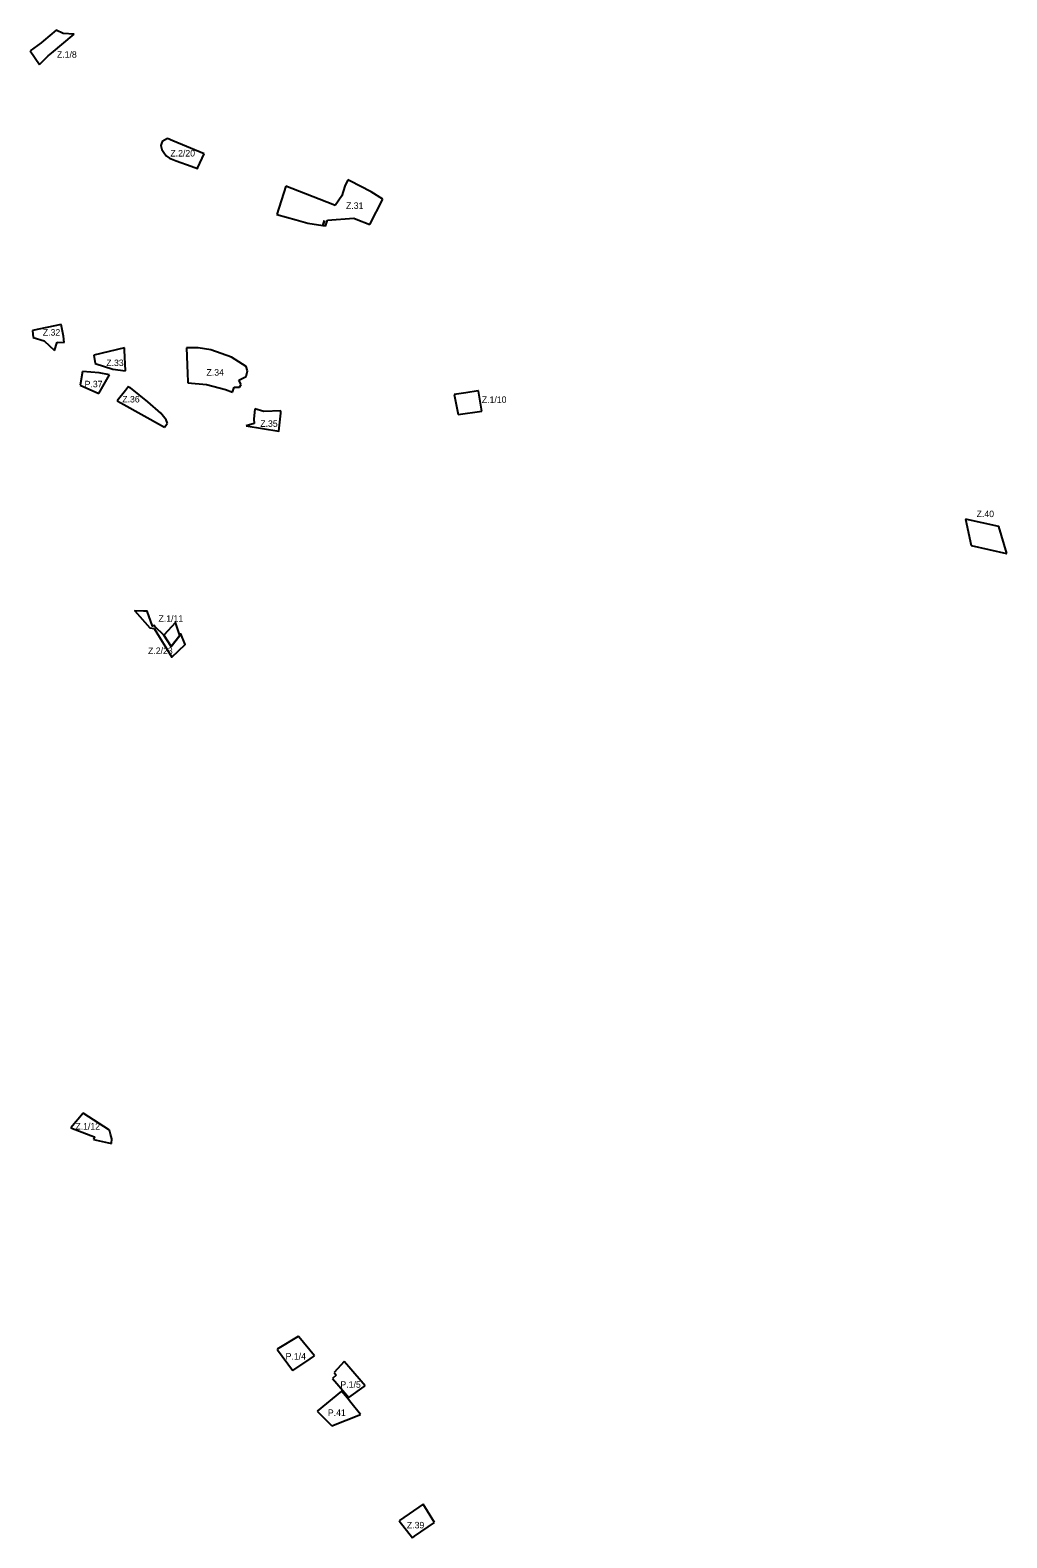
# Model space of a CAD drawing. Extents: x -438701 to -435614, y -1126017 to -1121766.
# Drawn here: x -437116 to -435614, y -1126017 to -1123697 of the extents above; entities that cross this region are included whole.
import ezdxf

# ---------------------------------------------------------------- set-up
doc = ezdxf.new("R2010")
doc.units = 0
for name, color, linetype in [('NAVRH', 7, 'Continuous'), ('STAV', 7, 'Continuous'), ('Vrstva 3', 7, 'Continuous'), ('Vrstva 6', 7, 'Continuous'), ('Vrstva 7', 7, 'Continuous'), ('Vrstva 9', 7, 'Continuous')]:
    doc.layers.add(name, color=color, linetype=linetype)

msp = doc.modelspace()

# ---------------------------------------------------------------- linework, layer by layer
at = {"layer": 'NAVRH'}
for p, q in [((-437083.4, -1123732.5), (-437048.4, -1123703.3)), ((-437048.4, -1123703.3), (-437065.4, -1123702.4)), ((-437099.4, -1123716.9), (-437116.3, -1123729)), ((-437116.3, -1123729), (-437101.9, -1123750.4)), ((-437095.9, -1123713.9), (-437099.4, -1123716.9)), ((-437101.9, -1123750.4), (-437088.6, -1123737)), ((-437088.6, -1123737), (-437083.4, -1123732.5)), ((-436905.2, -1123864.2), (-436913, -1123868.5)), ((-436896.8, -1123867.7), (-436905.2, -1123864.2)), ((-436848.6, -1123887.5), (-436896.8, -1123867.7)), ((-436858.2, -1123908.4), (-436848.6, -1123887.5)), ((-436902.2, -1123894.4), (-436891.8, -1123898.2)), ((-436891.8, -1123898.2), (-436868.4, -1123906.8)), ((-436722.9, -1123937.2), (-436736.8, -1123981)), ((-436650.9, -1123965.6), (-436722.9, -1123937.2)), ((-436632.1, -1123937.3), (-436636.8, -1123952)), ((-436627.7, -1123927.6), (-436632.1, -1123937.3)), ((-436624.3, -1123929.2), (-436627.7, -1123927.6)), ((-436591.6, -1123946.3), (-436624.3, -1123929.2)), ((-436636.8, -1123952), (-436647.2, -1123967)), ((-436593.6, -1123996.5), (-436574, -1123957.5)), ((-436574, -1123957.5), (-436591.6, -1123946.3)), ((-436736.8, -1123981), (-436707, -1123989.2)), ((-436647.2, -1123967), (-436650.9, -1123965.6)), ((-436707, -1123989.2), (-436689.2, -1123994.1)), ((-436689.2, -1123994.1), (-436666.1, -1123998)), ((-436666.1, -1123998), (-436663.7, -1123989.9)), ((-436663.7, -1123989.9), (-436666.1, -1123998)), ((-436666.1, -1123998), (-436662.4, -1123998.6)), ((-436662.4, -1123998.6), (-436661.9, -1123998.7)), ((-436661.9, -1123998.7), (-436659.1, -1123989.5)), ((-436659.1, -1123989.5), (-436618.6, -1123986.4)), ((-436618.6, -1123986.4), (-436614.7, -1123988.1)), ((-436614.7, -1123988.1), (-436593.6, -1123996.5)), ((-437068.7, -1124150.4), (-437112.6, -1124159.2)), ((-437112.6, -1124159.2), (-437111.6, -1124170.1)), ((-437065, -1124168.2), (-437068.7, -1124150.4)), ((-437064, -1124177.9), (-437065, -1124168.2)), ((-437111.6, -1124170.1), (-437094.7, -1124175.4)), ((-437094.7, -1124175.4), (-437079.1, -1124190.4)), ((-437079.1, -1124190.4), (-437074.6, -1124177.5)), ((-437074.6, -1124177.5), (-437064, -1124177.9)), ((-436971.4, -1124186), (-437018.1, -1124197.5)), ((-436858.1, -1124186.2), (-436875.8, -1124186.2)), ((-436875.8, -1124186.2), (-436874.4, -1124225.7)), ((-436838.3, -1124189.2), (-436858.1, -1124186.2)), ((-436806.4, -1124200.6), (-436838.3, -1124189.2)), ((-437018.1, -1124197.5), (-437016.3, -1124210.4)), ((-437016.3, -1124210.4), (-436989, -1124218.8)), ((-436989, -1124218.8), (-436969.5, -1124221.3)), ((-436795.2, -1124235.9), (-436783.9, -1124229.9)), ((-436791.6, -1124242.4), (-436795.2, -1124235.9)), ((-436783.9, -1124229.9), (-436782.2, -1124221.6)), ((-436969.8, -1124251.8), (-436982.2, -1124267.5)), ((-436964.8, -1124245.5), (-436969.8, -1124251.8)), ((-436962.5, -1124247.4), (-436964.8, -1124245.5)), ((-436962, -1124247.8), (-436962.5, -1124247.4)), ((-436935.2, -1124269.2), (-436962, -1124247.8)), ((-436873.8, -1124240.1), (-436844.8, -1124242.4)), ((-436844.8, -1124242.4), (-436815.8, -1124250.1)), ((-436815.8, -1124250.1), (-436805.2, -1124254.3)), ((-436805.2, -1124254.3), (-436802.4, -1124246.6)), ((-436802.4, -1124246.6), (-436794.2, -1124246.6)), ((-436794.2, -1124246.6), (-436791.6, -1124242.4)), ((-436445.9, -1124255.1), (-436463.9, -1124257.7)), ((-436463.9, -1124257.7), (-436457.8, -1124288.6)), ((-436426.4, -1124252.6), (-436426.4, -1124252.3)), ((-436982.2, -1124267.5), (-436976.9, -1124270.5)), ((-436976.9, -1124270.5), (-436909.8, -1124308.1)), ((-436915.3, -1124286.8), (-436935.2, -1124269.2)), ((-436770.6, -1124280.1), (-436772.2, -1124295.9)), ((-436756.9, -1124283.9), (-436770.6, -1124280.1)), ((-436730.6, -1124283), (-436756.9, -1124283.9)), ((-436730.9, -1124286.5), (-436730.6, -1124283)), ((-436457.8, -1124288.6), (-436421.7, -1124283.6)), ((-436907.2, -1124296.7), (-436915.3, -1124286.8)), ((-436909.8, -1124308.1), (-436905.9, -1124303.6)), ((-436904.9, -1124302.6), (-436907.2, -1124296.7)), ((-436905.9, -1124303.6), (-436904.9, -1124302.6)), ((-436771.6, -1124302.6), (-436784.1, -1124306.3)), ((-436772.2, -1124295.9), (-436771.6, -1124302.6)), ((-436733.1, -1124309.7), (-436730.9, -1124286.5)), ((-435677.7, -1124449.5), (-435668.6, -1124490.1)), ((-437034.5, -1125363.7), (-437053.9, -1125386)), ((-436994.4, -1125389.4), (-437034.5, -1125363.7)), ((-437053.9, -1125386), (-437022.8, -1125397.9)), ((-436992.8, -1125395.8), (-436994.4, -1125389.4)), ((-436990.8, -1125403), (-436992.8, -1125395.8)), ((-437018.9, -1125404), (-436991.1, -1125410.3)), ((-436991.1, -1125410.3), (-436990.8, -1125403)), ((-436511.7, -1125965.3), (-436547.9, -1125990.4)), ((-436494.2, -1125993.2), (-436511.7, -1125965.3)), ((-436547.9, -1125990.4), (-436548.7, -1125990.9)), ((-436548.7, -1125990.9), (-436528.2, -1126016.9)), ((-436524.9, -1126014.5), (-436494.2, -1125993.2)), ((-436528.2, -1126016.9), (-436524.9, -1126014.5))]:
    msp.add_line(p, q, dxfattribs=at)
for points in [[(-437065.4, -1123702.4), (-437076.5, -1123697.3), (-437095.9, -1123713.9)], [(-436913, -1123868.5), (-436915.2, -1123874.8), (-436913.5, -1123880.9), (-436910.9, -1123885.7), (-436907.2, -1123890.6), (-436902.2, -1123894.4)], [(-436868.4, -1123906.8), (-436859, -1123910.2), (-436858.2, -1123908.4)], [(-436969.5, -1124221.3), (-436971.2, -1124189.7), (-436971.4, -1124186)], [(-436782.2, -1124221.6), (-436783.8, -1124214.7), (-436806.4, -1124200.6)], [(-436874.4, -1124225.7), (-436873.9, -1124237.6), (-436873.8, -1124240.1)], [(-436426.4, -1124252.3), (-436427, -1124252.4), (-436445.9, -1124255.1)], [(-436421.7, -1124283.6), (-436421.7, -1124283.4), (-436426.4, -1124252.6)], [(-436784.1, -1124306.3), (-436733.8, -1124314.3), (-436733.1, -1124309.7)], [(-435613.9, -1124502.6), (-435626, -1124460.9), (-435677.7, -1124449.5)], [(-435668.6, -1124490.1), (-435614.2, -1124502.5), (-435613.9, -1124502.6)], [(-436910.8, -1124628.3), (-436924.2, -1124615.3), (-436925.2, -1124613), (-436928.1, -1124614.1), (-436936.3, -1124591.2), (-436941.8, -1124591.2), (-436955.5, -1124590.9), (-436932.2, -1124617), (-436925.5, -1124618), (-436898.2, -1124662.2), (-436877.8, -1124642.5), (-436884.3, -1124626.3), (-436886.2, -1124628.7)], [(-436886.2, -1124628.7), (-436892.8, -1124608.8), (-436910.8, -1124628.3)], [(-436886.2, -1124628.7), (-436899.3, -1124645.8), (-436910.8, -1124628.3)], [(-436910.8, -1124628.3), (-436899.3, -1124645.8), (-436886.2, -1124628.7)], [(-437022.8, -1125397.9), (-437017.4, -1125400), (-437018.9, -1125404)]]:
    msp.add_lwpolyline(points, dxfattribs=at)
at = {"layer": 'Vrstva 3'}
for p, q in [((-437036, -1124222.5), (-437039.4, -1124243.7)), ((-437010.4, -1124256.5), (-436994, -1124227.8)), ((-437039.4, -1124243.7), (-437010.4, -1124256.5)), ((-436703.8, -1125707.2), (-436736.4, -1125726.8)), ((-436736.4, -1125726.8), (-436735.8, -1125727.8)), ((-436633.2, -1125745.4), (-436648.8, -1125762.5)), ((-436626.2, -1125753.6), (-436633.2, -1125745.4)), ((-436645.4, -1125766.4), (-436651.2, -1125771.9)), ((-436648.8, -1125762.5), (-436645.4, -1125766.4)), ((-436601.2, -1125782.8), (-436626.2, -1125753.6)), ((-436637.5, -1125791.1), (-436674.7, -1125822.2)), ((-436651.2, -1125771.9), (-436644.8, -1125779.3)), ((-436644.8, -1125779.3), (-436626.2, -1125800.9)), ((-436628.1, -1125802.2), (-436637.5, -1125791.1)), ((-436626.2, -1125800.9), (-436602.6, -1125783.9)), ((-436602.6, -1125783.9), (-436601.2, -1125782.8)), ((-436623.1, -1125808.4), (-436628.1, -1125802.2)), ((-436608.1, -1125827.2), (-436623.1, -1125808.4)), ((-436674.7, -1125822.2), (-436663.5, -1125833.4)), ((-436663.5, -1125833.4), (-436652.4, -1125844.6)), ((-436652.4, -1125844.6), (-436608.1, -1125827.2))]:
    msp.add_line(p, q, dxfattribs=at)
for points in [[(-436994, -1124227.8), (-437009.9, -1124224.6), (-437036, -1124222.5)], [(-436679, -1125736.7), (-436702.8, -1125707.8), (-436703.8, -1125707.2)], [(-436735.8, -1125727.8), (-436712.6, -1125759.1), (-436712.4, -1125759.4)], [(-436712.4, -1125759.4), (-436685.7, -1125741.2), (-436679, -1125736.7)]]:
    msp.add_lwpolyline(points, dxfattribs=at)
at = {"layer": 'Vrstva 6'}
for p, q in [((-437083.4, -1123732.5), (-437048.4, -1123703.3)), ((-437048.4, -1123703.3), (-437065.4, -1123702.4)), ((-437099.4, -1123716.9), (-437116.3, -1123729)), ((-437116.3, -1123729), (-437101.9, -1123750.4)), ((-437095.9, -1123713.9), (-437099.4, -1123716.9)), ((-437101.9, -1123750.4), (-437088.6, -1123737)), ((-437088.6, -1123737), (-437083.4, -1123732.5)), ((-436905.2, -1123864.2), (-436913, -1123868.5)), ((-436896.8, -1123867.7), (-436905.2, -1123864.2)), ((-436848.6, -1123887.5), (-436896.8, -1123867.7)), ((-436858.2, -1123908.4), (-436848.6, -1123887.5)), ((-436902.2, -1123894.4), (-436891.8, -1123898.2)), ((-436891.8, -1123898.2), (-436868.4, -1123906.8)), ((-436722.9, -1123937.2), (-436736.8, -1123981)), ((-436650.9, -1123965.6), (-436722.9, -1123937.2)), ((-436632.1, -1123937.3), (-436636.8, -1123952)), ((-436627.7, -1123927.6), (-436632.1, -1123937.3)), ((-436624.3, -1123929.2), (-436627.7, -1123927.6)), ((-436591.6, -1123946.3), (-436624.3, -1123929.2)), ((-436636.8, -1123952), (-436647.2, -1123967)), ((-436593.6, -1123996.5), (-436574, -1123957.5)), ((-436574, -1123957.5), (-436591.6, -1123946.3)), ((-436736.8, -1123981), (-436707, -1123989.2)), ((-436647.2, -1123967), (-436650.9, -1123965.6)), ((-436707, -1123989.2), (-436689.2, -1123994.1)), ((-436689.2, -1123994.1), (-436666.1, -1123998)), ((-436666.1, -1123998), (-436663.7, -1123989.9)), ((-436663.7, -1123989.9), (-436666.1, -1123998)), ((-436666.1, -1123998), (-436662.4, -1123998.6)), ((-436662.4, -1123998.6), (-436661.9, -1123998.7)), ((-436661.9, -1123998.7), (-436659.1, -1123989.5)), ((-436659.1, -1123989.5), (-436618.6, -1123986.4)), ((-436618.6, -1123986.4), (-436614.7, -1123988.1)), ((-436614.7, -1123988.1), (-436593.6, -1123996.5)), ((-437068.7, -1124150.4), (-437112.6, -1124159.2)), ((-437112.6, -1124159.2), (-437111.6, -1124170.1)), ((-437065, -1124168.2), (-437068.7, -1124150.4)), ((-437064, -1124177.9), (-437065, -1124168.2)), ((-437111.6, -1124170.1), (-437094.7, -1124175.4)), ((-437094.7, -1124175.4), (-437079.1, -1124190.4)), ((-437079.1, -1124190.4), (-437074.6, -1124177.5)), ((-437074.6, -1124177.5), (-437064, -1124177.9)), ((-436971.4, -1124186), (-437018.1, -1124197.5)), ((-436858.1, -1124186.2), (-436875.8, -1124186.2)), ((-436875.8, -1124186.2), (-436874.4, -1124225.7)), ((-436838.3, -1124189.2), (-436858.1, -1124186.2)), ((-436806.4, -1124200.6), (-436838.3, -1124189.2)), ((-437018.1, -1124197.5), (-437016.3, -1124210.4)), ((-437016.3, -1124210.4), (-436989, -1124218.8)), ((-436989, -1124218.8), (-436969.5, -1124221.3)), ((-436795.2, -1124235.9), (-436783.9, -1124229.9)), ((-436791.6, -1124242.4), (-436795.2, -1124235.9)), ((-436783.9, -1124229.9), (-436782.2, -1124221.6)), ((-436969.8, -1124251.8), (-436982.2, -1124267.5)), ((-436964.8, -1124245.5), (-436969.8, -1124251.8)), ((-436962.5, -1124247.4), (-436964.8, -1124245.5)), ((-436962, -1124247.8), (-436962.5, -1124247.4)), ((-436935.2, -1124269.2), (-436962, -1124247.8)), ((-436873.8, -1124240.1), (-436844.8, -1124242.4)), ((-436844.8, -1124242.4), (-436815.8, -1124250.1)), ((-436815.8, -1124250.1), (-436805.2, -1124254.3)), ((-436805.2, -1124254.3), (-436802.4, -1124246.6)), ((-436802.4, -1124246.6), (-436794.2, -1124246.6)), ((-436794.2, -1124246.6), (-436791.6, -1124242.4)), ((-436445.9, -1124255.1), (-436463.9, -1124257.7)), ((-436463.9, -1124257.7), (-436457.8, -1124288.6)), ((-436426.4, -1124252.6), (-436426.4, -1124252.3)), ((-436982.2, -1124267.5), (-436976.9, -1124270.5)), ((-436976.9, -1124270.5), (-436909.8, -1124308.1)), ((-436915.3, -1124286.8), (-436935.2, -1124269.2)), ((-436770.6, -1124280.1), (-436772.2, -1124295.9)), ((-436756.9, -1124283.9), (-436770.6, -1124280.1)), ((-436730.6, -1124283), (-436756.9, -1124283.9)), ((-436730.9, -1124286.5), (-436730.6, -1124283)), ((-436457.8, -1124288.6), (-436421.7, -1124283.6)), ((-436907.2, -1124296.7), (-436915.3, -1124286.8)), ((-436909.8, -1124308.1), (-436905.9, -1124303.6)), ((-436904.9, -1124302.6), (-436907.2, -1124296.7)), ((-436905.9, -1124303.6), (-436904.9, -1124302.6)), ((-436771.6, -1124302.6), (-436784.1, -1124306.3)), ((-436772.2, -1124295.9), (-436771.6, -1124302.6)), ((-436733.1, -1124309.7), (-436730.9, -1124286.5)), ((-435677.7, -1124449.5), (-435668.6, -1124490.1)), ((-436899.3, -1124645.8), (-436910.8, -1124628.3)), ((-436910.8, -1124628.3), (-436899.3, -1124645.8)), ((-436886.2, -1124628.7), (-436899.3, -1124645.8)), ((-436899.3, -1124645.8), (-436886.2, -1124628.7)), ((-437034.5, -1125363.7), (-437053.9, -1125386)), ((-436994.4, -1125389.4), (-437034.5, -1125363.7)), ((-437053.9, -1125386), (-437022.8, -1125397.9)), ((-436992.8, -1125395.8), (-436994.4, -1125389.4)), ((-436990.8, -1125403), (-436992.8, -1125395.8)), ((-437018.9, -1125404), (-436991.1, -1125410.3)), ((-436991.1, -1125410.3), (-436990.8, -1125403)), ((-436511.7, -1125965.3), (-436547.9, -1125990.4)), ((-436494.2, -1125993.2), (-436511.7, -1125965.3)), ((-436547.9, -1125990.4), (-436548.7, -1125990.9)), ((-436548.7, -1125990.9), (-436528.2, -1126016.9)), ((-436524.9, -1126014.5), (-436494.2, -1125993.2)), ((-436528.2, -1126016.9), (-436524.9, -1126014.5))]:
    msp.add_line(p, q, dxfattribs=at)
for points in [[(-437065.4, -1123702.4), (-437076.5, -1123697.3), (-437095.9, -1123713.9)], [(-436913, -1123868.5), (-436915.2, -1123874.8), (-436913.5, -1123880.9), (-436910.9, -1123885.7), (-436907.2, -1123890.6), (-436902.2, -1123894.4)], [(-436868.4, -1123906.8), (-436859, -1123910.2), (-436858.2, -1123908.4)], [(-436969.5, -1124221.3), (-436971.2, -1124189.7), (-436971.4, -1124186)], [(-436782.2, -1124221.6), (-436783.8, -1124214.7), (-436806.4, -1124200.6)], [(-436874.4, -1124225.7), (-436873.9, -1124237.6), (-436873.8, -1124240.1)], [(-436426.4, -1124252.3), (-436427, -1124252.4), (-436445.9, -1124255.1)], [(-436421.7, -1124283.6), (-436421.7, -1124283.4), (-436426.4, -1124252.6)], [(-436784.1, -1124306.3), (-436733.8, -1124314.3), (-436733.1, -1124309.7)], [(-435613.9, -1124502.6), (-435626, -1124460.9), (-435677.7, -1124449.5)], [(-435668.6, -1124490.1), (-435614.2, -1124502.5), (-435613.9, -1124502.6)], [(-436910.8, -1124628.3), (-436924.2, -1124615.3), (-436925.2, -1124613), (-436928.1, -1124614.1), (-436936.3, -1124591.2), (-436941.8, -1124591.2), (-436955.5, -1124590.9), (-436932.2, -1124617), (-436925.5, -1124618), (-436898.2, -1124662.2), (-436877.8, -1124642.5), (-436884.3, -1124626.3), (-436886.2, -1124628.7)], [(-436886.2, -1124628.7), (-436892.8, -1124608.8), (-436910.8, -1124628.3)], [(-437022.8, -1125397.9), (-437017.4, -1125400), (-437018.9, -1125404)]]:
    msp.add_lwpolyline(points, dxfattribs=at)
at = {"layer": 'Vrstva 7'}
for p, q in [((-437036, -1124222.5), (-437039.4, -1124243.7)), ((-437010.4, -1124256.5), (-436994, -1124227.8)), ((-437039.4, -1124243.7), (-437010.4, -1124256.5)), ((-436703.8, -1125707.2), (-436736.4, -1125726.8)), ((-436736.4, -1125726.8), (-436735.8, -1125727.8)), ((-436633.2, -1125745.4), (-436648.8, -1125762.5)), ((-436626.2, -1125753.6), (-436633.2, -1125745.4)), ((-436645.4, -1125766.4), (-436651.2, -1125771.9)), ((-436648.8, -1125762.5), (-436645.4, -1125766.4)), ((-436601.2, -1125782.8), (-436626.2, -1125753.6)), ((-436637.5, -1125791.1), (-436674.7, -1125822.2)), ((-436651.2, -1125771.9), (-436644.8, -1125779.3)), ((-436644.8, -1125779.3), (-436626.2, -1125800.9)), ((-436628.1, -1125802.2), (-436637.5, -1125791.1)), ((-436626.2, -1125800.9), (-436602.6, -1125783.9)), ((-436602.6, -1125783.9), (-436601.2, -1125782.8)), ((-436623.1, -1125808.4), (-436628.1, -1125802.2)), ((-436608.1, -1125827.2), (-436623.1, -1125808.4)), ((-436674.7, -1125822.2), (-436663.5, -1125833.4)), ((-436663.5, -1125833.4), (-436652.4, -1125844.6)), ((-436652.4, -1125844.6), (-436608.1, -1125827.2))]:
    msp.add_line(p, q, dxfattribs=at)
for points in [[(-436994, -1124227.8), (-437009.9, -1124224.6), (-437036, -1124222.5)], [(-436679, -1125736.7), (-436702.8, -1125707.8), (-436703.8, -1125707.2)], [(-436735.8, -1125727.8), (-436712.6, -1125759.1), (-436712.4, -1125759.4)], [(-436712.4, -1125759.4), (-436685.7, -1125741.2), (-436679, -1125736.7)]]:
    msp.add_lwpolyline(points, dxfattribs=at)

# ---------------------------------------------------------------- texts
at = {"layer": 'STAV'}
for s, p in [('P.37', (-437032.5, -1124246.8)), ('P.1/4', (-436723.3, -1125742.6)), ('P.1/5', (-436639, -1125786)), ('P.41', (-436658.3, -1125829.3))]:
    msp.add_text(s, height=10, dxfattribs=at).set_placement(p)
at = {"layer": 'Vrstva 9'}
for s, p in [('Z.1/8', (-437075.1, -1123739.8)), ('Z.2/20', (-436900.6, -1123891.7)), ('Z.31', (-436630.4, -1123972.3)), ('Z.32', (-437096.8, -1124167.2)), ('Z.33', (-436999.2, -1124214.1)), ('Z.34', (-436845, -1124228.8)), ('Z.36', (-436974.6, -1124270.1)), ('Z.1/10', (-436421.5, -1124270.8)), ('Z.35', (-436762.3, -1124307.6)), ('Z.40', (-435660.4, -1124446.5)), ('Z.1/11', (-436918.8, -1124607.5)), ('Z.2/23', (-436934.9, -1124657.1)), ('Z.1/12', (-437046.7, -1125388.7)), ('Z.39', (-436536.8, -1126002.3))]:
    msp.add_text(s, height=10, dxfattribs=at).set_placement(p)

doc.saveas('drawing.dxf')
